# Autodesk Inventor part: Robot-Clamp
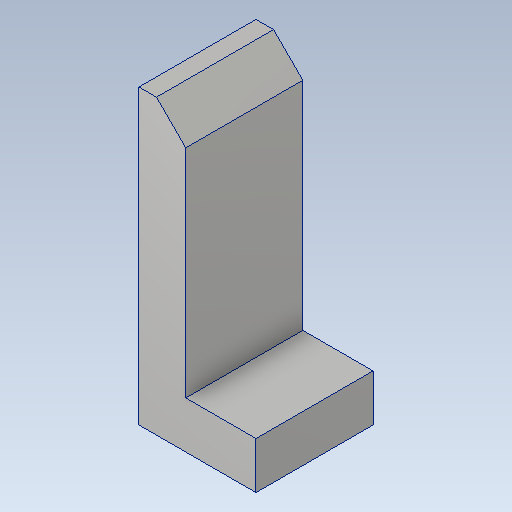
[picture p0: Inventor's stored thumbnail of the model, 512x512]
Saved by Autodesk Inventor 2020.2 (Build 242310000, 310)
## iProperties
Created: 2018-07
Part Number: Robot-Clamp
Material: Aluminum 6061
Description: 123456
Document SubType Name: Modeling
Designer: Power User
Mass: 26.109 g
Surface Area: 37.0842 cm^2
Volume: 9.67 cm^3
Density: 2.7 g/cm^3
Appearance: Aluminum - Flat
Author: Power User
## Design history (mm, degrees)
sketch "Sketch6"
  geometry: L1 (0, 0)-(0, 50); L2 (0, 50)-(8, 50); L3 (8, 50)-(8, 8); L4 (8, 8)-(20, 8); L5 (20, 8)-(20, 0); L6 (20, 0)-(0, 0)
  constraints: 12 end point, 5 perpendicular, 1 vertical
  dimensions: "d44" = 20 distance of L5.end L1.start; "d45" = 12 distance of L3.end L4.end; "d46" = 50 distance of L1.start L1.end; "d47" = 8 distance of L4.end L5.end
extrude "Extrusion5" new body sketch "Sketch6" stored distance "d48" = 20; taper "d49" = 0 deg
chamfer "Chamfer2" distance "d50" = 5; stored, may be unused: second distance "d51" = 5, angle "d52" = 45 deg
body "Solid2"
